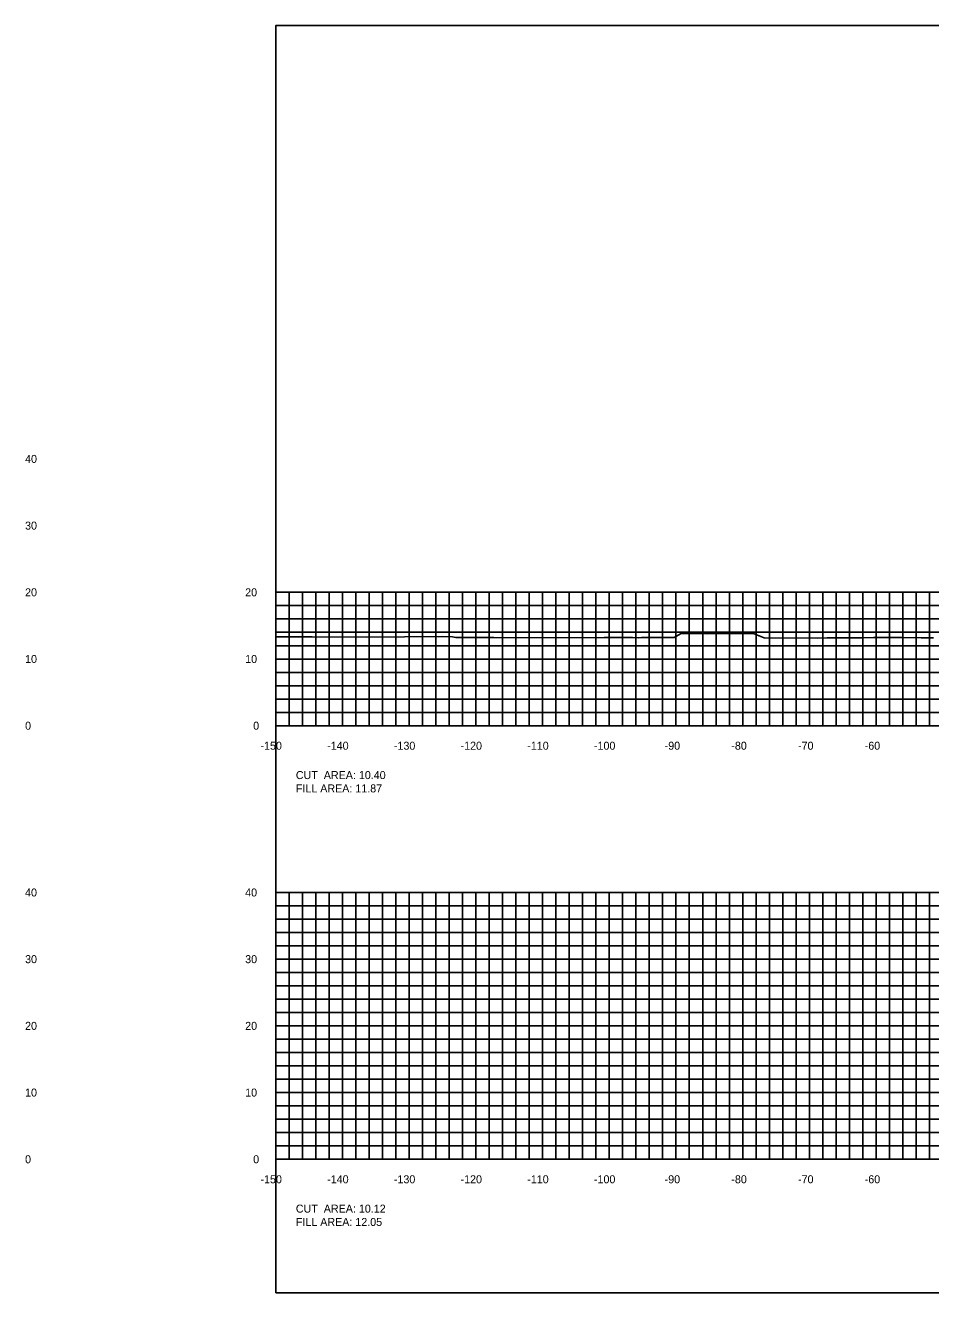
# Model space of a CAD drawing. Extents: x 1797645 to 1803805, y 248417 to 250269.
# Drawn here: x 1803463.4 to 1803599.2, y 250079.4 to 250269.4 of the extents above; entities that cross this region are included whole.
import ezdxf

# ---------------------------------------------------------------- set-up
doc = ezdxf.new("R2010")
doc.units = 0
for name, color, linetype in [('10', 7, 'Continuous'), ('31', 7, 'Continuous'), ('60', 7, 'Continuous'), ('ANNO-TXT', 7, 'Continuous'), ('Level 62', 7, 'Continuous'), ('M-ROADS', 7, 'Continuous')]:
    doc.layers.add(name, color=color, linetype=linetype)

msp = doc.modelspace()

# ---------------------------------------------------------------- linework, layer by layer
msp.add_lwpolyline([(1803501, 250079.43), (1803801, 250079.43), (1803801, 250269.43), (1803501, 250269.43)], close=True)
at = {"layer": '60'}
for p, q in [((1803500.94, 250184.43), (1803501, 250184.43)), ((1803501, 250164.43), (1803501, 250184.43)), ((1803500.94, 250174.43), (1803501, 250174.43)), ((1803500.94, 250164.43), (1803501, 250164.43)), ((1803501, 250164.43), (1803801, 250164.43)), ((1803501, 250164.37), (1803501, 250164.43)), ((1803511, 250164.37), (1803511, 250164.43)), ((1803521, 250164.37), (1803521, 250164.43)), ((1803531, 250164.37), (1803531, 250164.43)), ((1803541, 250164.37), (1803541, 250164.43)), ((1803551, 250164.37), (1803551, 250164.43)), ((1803561, 250164.37), (1803561, 250164.43)), ((1803571, 250164.37), (1803571, 250164.43)), ((1803581, 250164.37), (1803581, 250164.43)), ((1803591, 250164.37), (1803591, 250164.43)), ((1803500.94, 250139.43), (1803501, 250139.43)), ((1803501, 250099.43), (1803501, 250139.43)), ((1803500.94, 250129.43), (1803501, 250129.43)), ((1803500.94, 250119.43), (1803501, 250119.43)), ((1803500.94, 250109.43), (1803501, 250109.43)), ((1803500.94, 250099.43), (1803501, 250099.43)), ((1803501, 250099.43), (1803801, 250099.43)), ((1803501, 250099.37), (1803501, 250099.43)), ((1803511, 250099.37), (1803511, 250099.43)), ((1803521, 250099.37), (1803521, 250099.43)), ((1803531, 250099.37), (1803531, 250099.43)), ((1803541, 250099.37), (1803541, 250099.43)), ((1803551, 250099.37), (1803551, 250099.43)), ((1803561, 250099.37), (1803561, 250099.43)), ((1803571, 250099.37), (1803571, 250099.43)), ((1803581, 250099.37), (1803581, 250099.43)), ((1803591, 250099.37), (1803591, 250099.43))]:
    msp.add_line(p, q, dxfattribs=at)
at = {"layer": 'Level 62'}
for p, q in [((1803501, 250184.43), (1803801, 250184.43)), ((1803501, 250164.43), (1803501, 250184.43)), ((1803503, 250164.43), (1803503, 250184.43)), ((1803505, 250164.43), (1803505, 250184.43)), ((1803507, 250164.43), (1803507, 250184.43)), ((1803509, 250164.43), (1803509, 250184.43)), ((1803511, 250164.43), (1803511, 250184.43)), ((1803513, 250164.43), (1803513, 250184.43)), ((1803515, 250164.43), (1803515, 250184.43)), ((1803517, 250164.43), (1803517, 250184.43)), ((1803519, 250164.43), (1803519, 250184.43)), ((1803521, 250164.43), (1803521, 250184.43)), ((1803523, 250164.43), (1803523, 250184.43)), ((1803525, 250164.43), (1803525, 250184.43)), ((1803527, 250164.43), (1803527, 250184.43)), ((1803529, 250164.43), (1803529, 250184.43)), ((1803531, 250164.43), (1803531, 250184.43)), ((1803533, 250164.43), (1803533, 250184.43)), ((1803535, 250164.43), (1803535, 250184.43)), ((1803537, 250164.43), (1803537, 250184.43)), ((1803539, 250164.43), (1803539, 250184.43)), ((1803541, 250164.43), (1803541, 250184.43)), ((1803543, 250164.43), (1803543, 250184.43)), ((1803545, 250164.43), (1803545, 250184.43)), ((1803547, 250164.43), (1803547, 250184.43)), ((1803549, 250164.43), (1803549, 250184.43)), ((1803551, 250164.43), (1803551, 250184.43)), ((1803553, 250164.43), (1803553, 250184.43)), ((1803555, 250164.43), (1803555, 250184.43)), ((1803557, 250164.43), (1803557, 250184.43)), ((1803559, 250164.43), (1803559, 250184.43)), ((1803561, 250164.43), (1803561, 250184.43)), ((1803563, 250164.43), (1803563, 250184.43)), ((1803565, 250164.43), (1803565, 250184.43)), ((1803567, 250164.43), (1803567, 250184.43)), ((1803569, 250164.43), (1803569, 250184.43)), ((1803571, 250164.43), (1803571, 250184.43)), ((1803573, 250164.43), (1803573, 250184.43)), ((1803575, 250164.43), (1803575, 250184.43)), ((1803577, 250164.43), (1803577, 250184.43)), ((1803579, 250164.43), (1803579, 250184.43)), ((1803581, 250164.43), (1803581, 250184.43)), ((1803583, 250164.43), (1803583, 250184.43)), ((1803585, 250164.43), (1803585, 250184.43)), ((1803587, 250164.43), (1803587, 250184.43)), ((1803589, 250164.43), (1803589, 250184.43)), ((1803591, 250164.43), (1803591, 250184.43)), ((1803593, 250164.43), (1803593, 250184.43)), ((1803595, 250164.43), (1803595, 250184.43)), ((1803597, 250164.43), (1803597, 250184.43)), ((1803599, 250164.43), (1803599, 250184.43)), ((1803501, 250182.43), (1803801, 250182.43)), ((1803501, 250180.43), (1803801, 250180.43)), ((1803501, 250178.43), (1803801, 250178.43)), ((1803501, 250176.43), (1803801, 250176.43)), ((1803501, 250174.43), (1803801, 250174.43)), ((1803501, 250172.43), (1803801, 250172.43)), ((1803501, 250170.43), (1803801, 250170.43)), ((1803501, 250168.43), (1803801, 250168.43)), ((1803501, 250166.43), (1803801, 250166.43)), ((1803501, 250164.43), (1803801, 250164.43)), ((1803501, 250139.43), (1803801, 250139.43)), ((1803501, 250099.43), (1803501, 250139.43)), ((1803503, 250099.43), (1803503, 250139.43)), ((1803505, 250099.43), (1803505, 250139.43)), ((1803507, 250099.43), (1803507, 250139.43)), ((1803509, 250099.43), (1803509, 250139.43)), ((1803511, 250099.43), (1803511, 250139.43)), ((1803513, 250099.43), (1803513, 250139.43)), ((1803515, 250099.43), (1803515, 250139.43)), ((1803517, 250099.43), (1803517, 250139.43)), ((1803519, 250099.43), (1803519, 250139.43)), ((1803521, 250099.43), (1803521, 250139.43)), ((1803523, 250099.43), (1803523, 250139.43)), ((1803525, 250099.43), (1803525, 250139.43)), ((1803527, 250099.43), (1803527, 250139.43)), ((1803529, 250099.43), (1803529, 250139.43)), ((1803531, 250099.43), (1803531, 250139.43)), ((1803533, 250099.43), (1803533, 250139.43)), ((1803535, 250099.43), (1803535, 250139.43)), ((1803537, 250099.43), (1803537, 250139.43)), ((1803539, 250099.43), (1803539, 250139.43)), ((1803541, 250099.43), (1803541, 250139.43)), ((1803543, 250099.43), (1803543, 250139.43)), ((1803545, 250099.43), (1803545, 250139.43)), ((1803547, 250099.43), (1803547, 250139.43)), ((1803549, 250099.43), (1803549, 250139.43)), ((1803551, 250099.43), (1803551, 250139.43)), ((1803553, 250099.43), (1803553, 250139.43)), ((1803555, 250099.43), (1803555, 250139.43)), ((1803557, 250099.43), (1803557, 250139.43)), ((1803559, 250099.43), (1803559, 250139.43)), ((1803561, 250099.43), (1803561, 250139.43)), ((1803563, 250099.43), (1803563, 250139.43)), ((1803565, 250099.43), (1803565, 250139.43)), ((1803567, 250099.43), (1803567, 250139.43)), ((1803569, 250099.43), (1803569, 250139.43)), ((1803571, 250099.43), (1803571, 250139.43)), ((1803573, 250099.43), (1803573, 250139.43)), ((1803575, 250099.43), (1803575, 250139.43)), ((1803577, 250099.43), (1803577, 250139.43)), ((1803579, 250099.43), (1803579, 250139.43)), ((1803581, 250099.43), (1803581, 250139.43)), ((1803583, 250099.43), (1803583, 250139.43)), ((1803585, 250099.43), (1803585, 250139.43)), ((1803587, 250099.43), (1803587, 250139.43)), ((1803589, 250099.43), (1803589, 250139.43)), ((1803591, 250099.43), (1803591, 250139.43)), ((1803593, 250099.43), (1803593, 250139.43)), ((1803595, 250099.43), (1803595, 250139.43)), ((1803597, 250099.43), (1803597, 250139.43)), ((1803599, 250099.43), (1803599, 250139.43)), ((1803501, 250137.43), (1803801, 250137.43)), ((1803501, 250135.43), (1803801, 250135.43)), ((1803501, 250133.43), (1803801, 250133.43)), ((1803501, 250131.43), (1803801, 250131.43)), ((1803501, 250129.43), (1803801, 250129.43)), ((1803501, 250127.43), (1803801, 250127.43)), ((1803501, 250125.43), (1803801, 250125.43)), ((1803501, 250123.43), (1803801, 250123.43)), ((1803501, 250121.43), (1803801, 250121.43)), ((1803501, 250119.43), (1803801, 250119.43)), ((1803501, 250117.43), (1803801, 250117.43)), ((1803501, 250115.43), (1803801, 250115.43)), ((1803501, 250113.43), (1803801, 250113.43)), ((1803501, 250111.43), (1803801, 250111.43)), ((1803501, 250109.43), (1803801, 250109.43)), ((1803501, 250107.43), (1803801, 250107.43)), ((1803501, 250105.43), (1803801, 250105.43)), ((1803501, 250103.43), (1803801, 250103.43)), ((1803501, 250101.43), (1803801, 250101.43)), ((1803501, 250099.43), (1803801, 250099.43))]:
    msp.add_line(p, q, dxfattribs=at)
at = {"layer": 'M-ROADS'}
msp.add_lwpolyline([(1803501, 250177.75), (1803502.32, 250177.74), (1803506.45, 250177.75), (1803514.58, 250177.7), (1803525.97, 250177.82), (1803527.51, 250177.74), (1803527.97, 250177.66), (1803528.9, 250177.66), (1803530.4, 250177.66), (1803532.62, 250177.66), (1803533.67, 250177.67), (1803547.08, 250177.63), (1803550.25, 250177.65), (1803553.18, 250177.66), (1803554.49, 250177.64), (1803555.34, 250177.62), (1803555.82, 250177.66), (1803556.04, 250177.64), (1803557.55, 250177.64), (1803560.75, 250177.66), (1803561.68, 250178.21), (1803563.98, 250178.28), (1803564.4, 250178.28), (1803564.75, 250178.28), (1803565.79, 250178.2), (1803571.23, 250178.24), (1803572.74, 250178.2), (1803574.2, 250177.61), (1803582.24, 250177.58), (1803583.66, 250177.61), (1803584.6, 250177.61), (1803586.4, 250177.62), (1803587.27, 250177.63), (1803588.96, 250177.63), (1803590.6, 250177.64), (1803591.7, 250177.64), (1803593.95, 250177.64), (1803594.89, 250177.64), (1803597.76, 250177.62), (1803599.6, 250177.61)], dxfattribs=at)

# ---------------------------------------------------------------- texts
at = {"layer": '10'}
for s, p in [('-150', (1803498.7, 250160.83)), ('-140', (1803508.7, 250160.83)), ('-130', (1803518.7, 250160.83)), ('-120', (1803528.7, 250160.83)), ('-110', (1803538.7, 250160.83)), ('-100', (1803548.7, 250160.83)), ('-90', (1803559.3, 250160.83)), ('-80', (1803569.3, 250160.83)), ('-70', (1803579.3, 250160.83)), ('-60', (1803589.3, 250160.83)), ('-150', (1803498.7, 250095.83)), ('-140', (1803508.7, 250095.83)), ('-130', (1803518.7, 250095.83)), ('-120', (1803528.7, 250095.83)), ('-110', (1803538.7, 250095.83)), ('-100', (1803548.7, 250095.83)), ('-90', (1803559.3, 250095.83)), ('-80', (1803569.3, 250095.83)), ('-70', (1803579.3, 250095.83)), ('-60', (1803589.3, 250095.83))]:
    msp.add_text(s, height=1.2, dxfattribs=at).set_placement(p)
at = {"layer": '31'}
for s, p in [('40', (1803463.4, 250203.83)), ('30', (1803463.4, 250193.83)), ('20', (1803463.4, 250183.83)), ('20', (1803496.4, 250183.83)), ('10', (1803463.4, 250173.83)), ('10', (1803496.4, 250173.83)), ('0', (1803463.4, 250163.83)), ('0', (1803497.6, 250163.83)), ('40', (1803463.4, 250138.83)), ('40', (1803496.4, 250138.83)), ('30', (1803463.4, 250128.83)), ('30', (1803496.4, 250128.83)), ('20', (1803463.4, 250118.83)), ('20', (1803496.4, 250118.83)), ('10', (1803463.4, 250108.83)), ('10', (1803496.4, 250108.83)), ('0', (1803463.4, 250098.83)), ('0', (1803497.6, 250098.83))]:
    msp.add_text(s, height=1.2, dxfattribs=at).set_placement(p)
at = {"layer": '60'}
for p in [(1803501, 250164.43), (1803501, 250099.43)]:
    msp.add_text('-', height=0.0001, dxfattribs=at).set_placement(p)
at = {"layer": 'ANNO-TXT'}
for s, p in [('CUT  AREA: 10.40', (1803504, 250156.43)), ('FILL AREA: 11.87', (1803504, 250154.43)), ('CUT  AREA: 10.12', (1803504, 250091.43)), ('FILL AREA: 12.05', (1803504, 250089.43))]:
    msp.add_text(s, height=1.2, dxfattribs=at).set_placement(p)

doc.saveas('drawing.dxf')
